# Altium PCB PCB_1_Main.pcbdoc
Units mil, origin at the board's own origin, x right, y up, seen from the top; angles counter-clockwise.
Board outline 3641.73 x 4338.58 mil, 2 copper layers (Top Layer, Bottom Layer), stack 62.206 mil thick; 67 components, 54 nets, 261 pads, 263 vias.
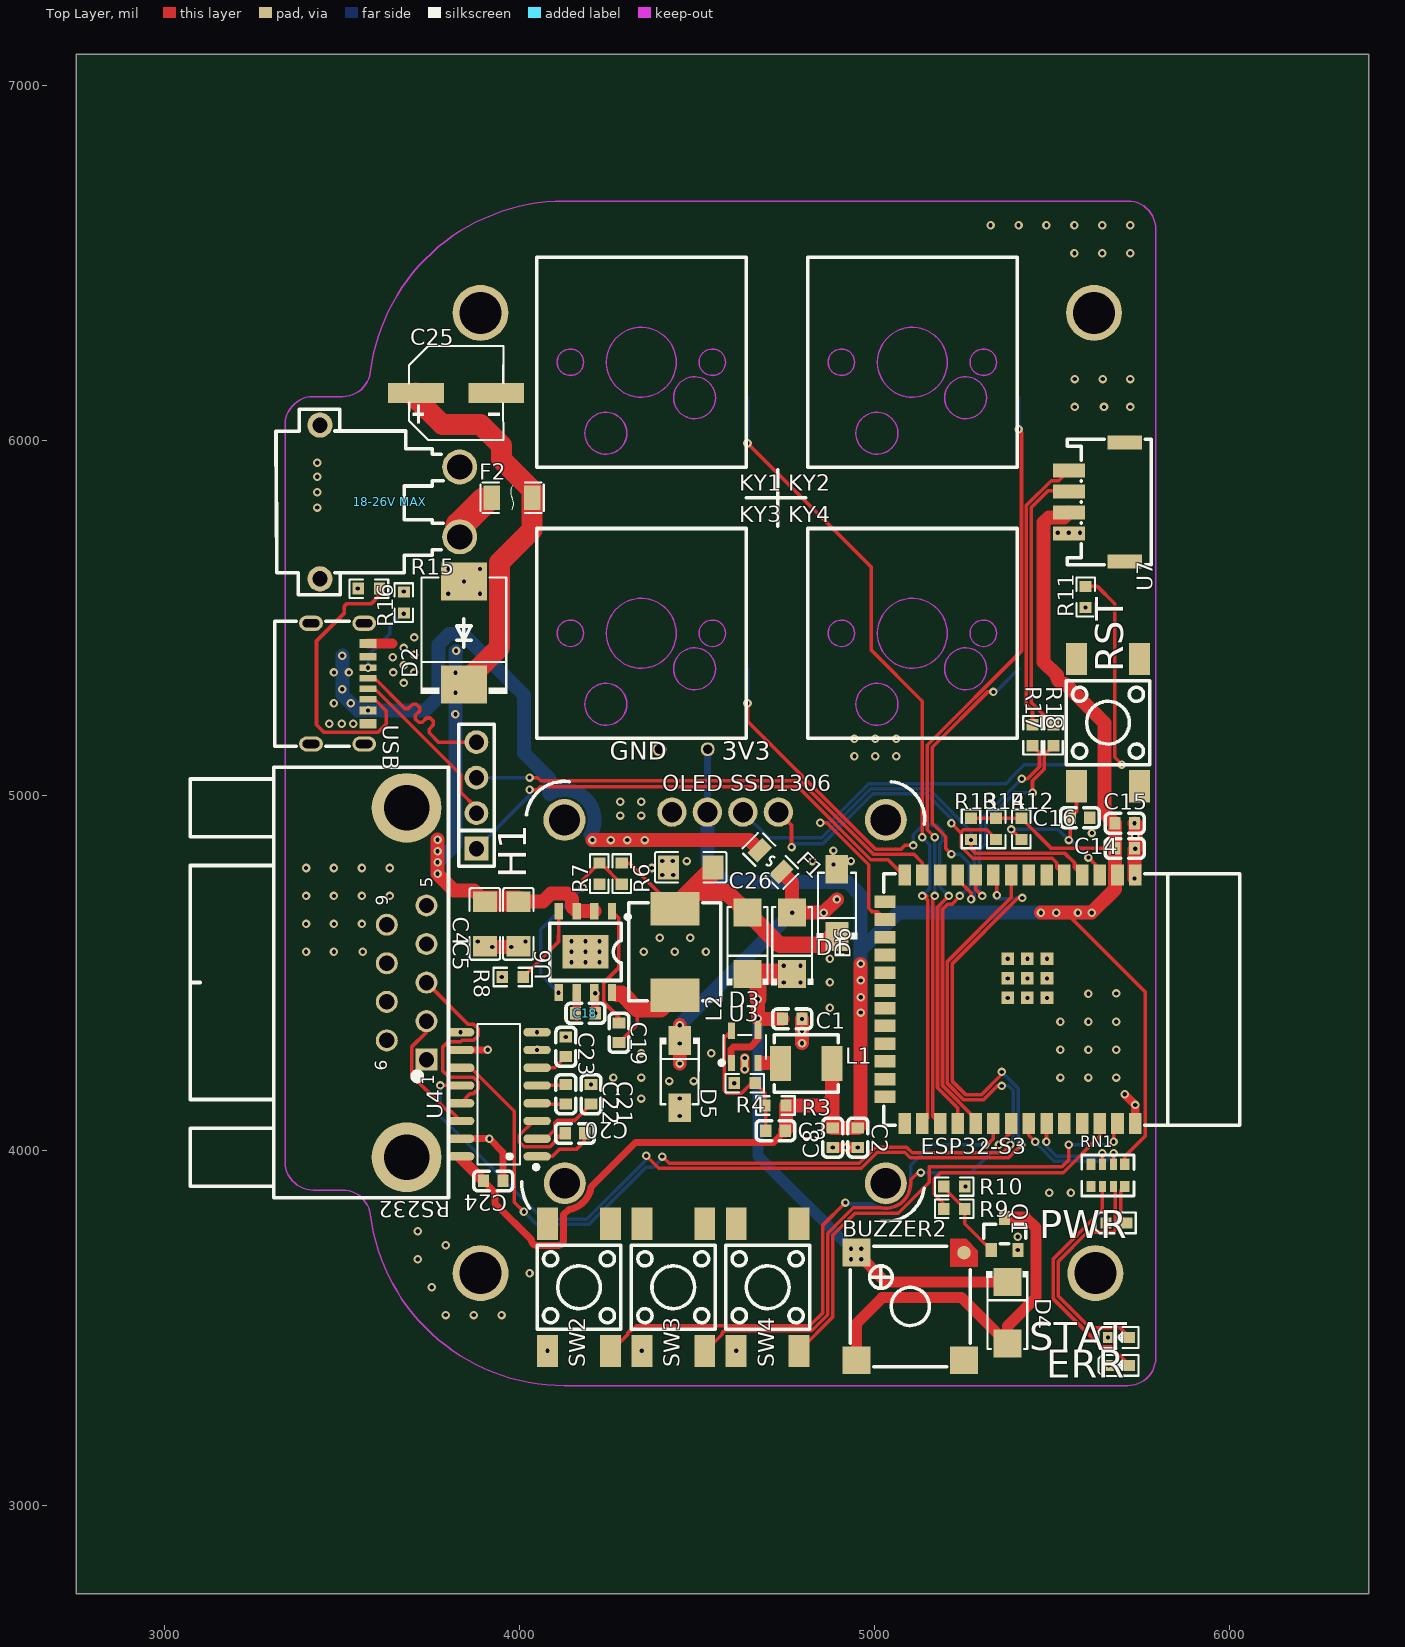
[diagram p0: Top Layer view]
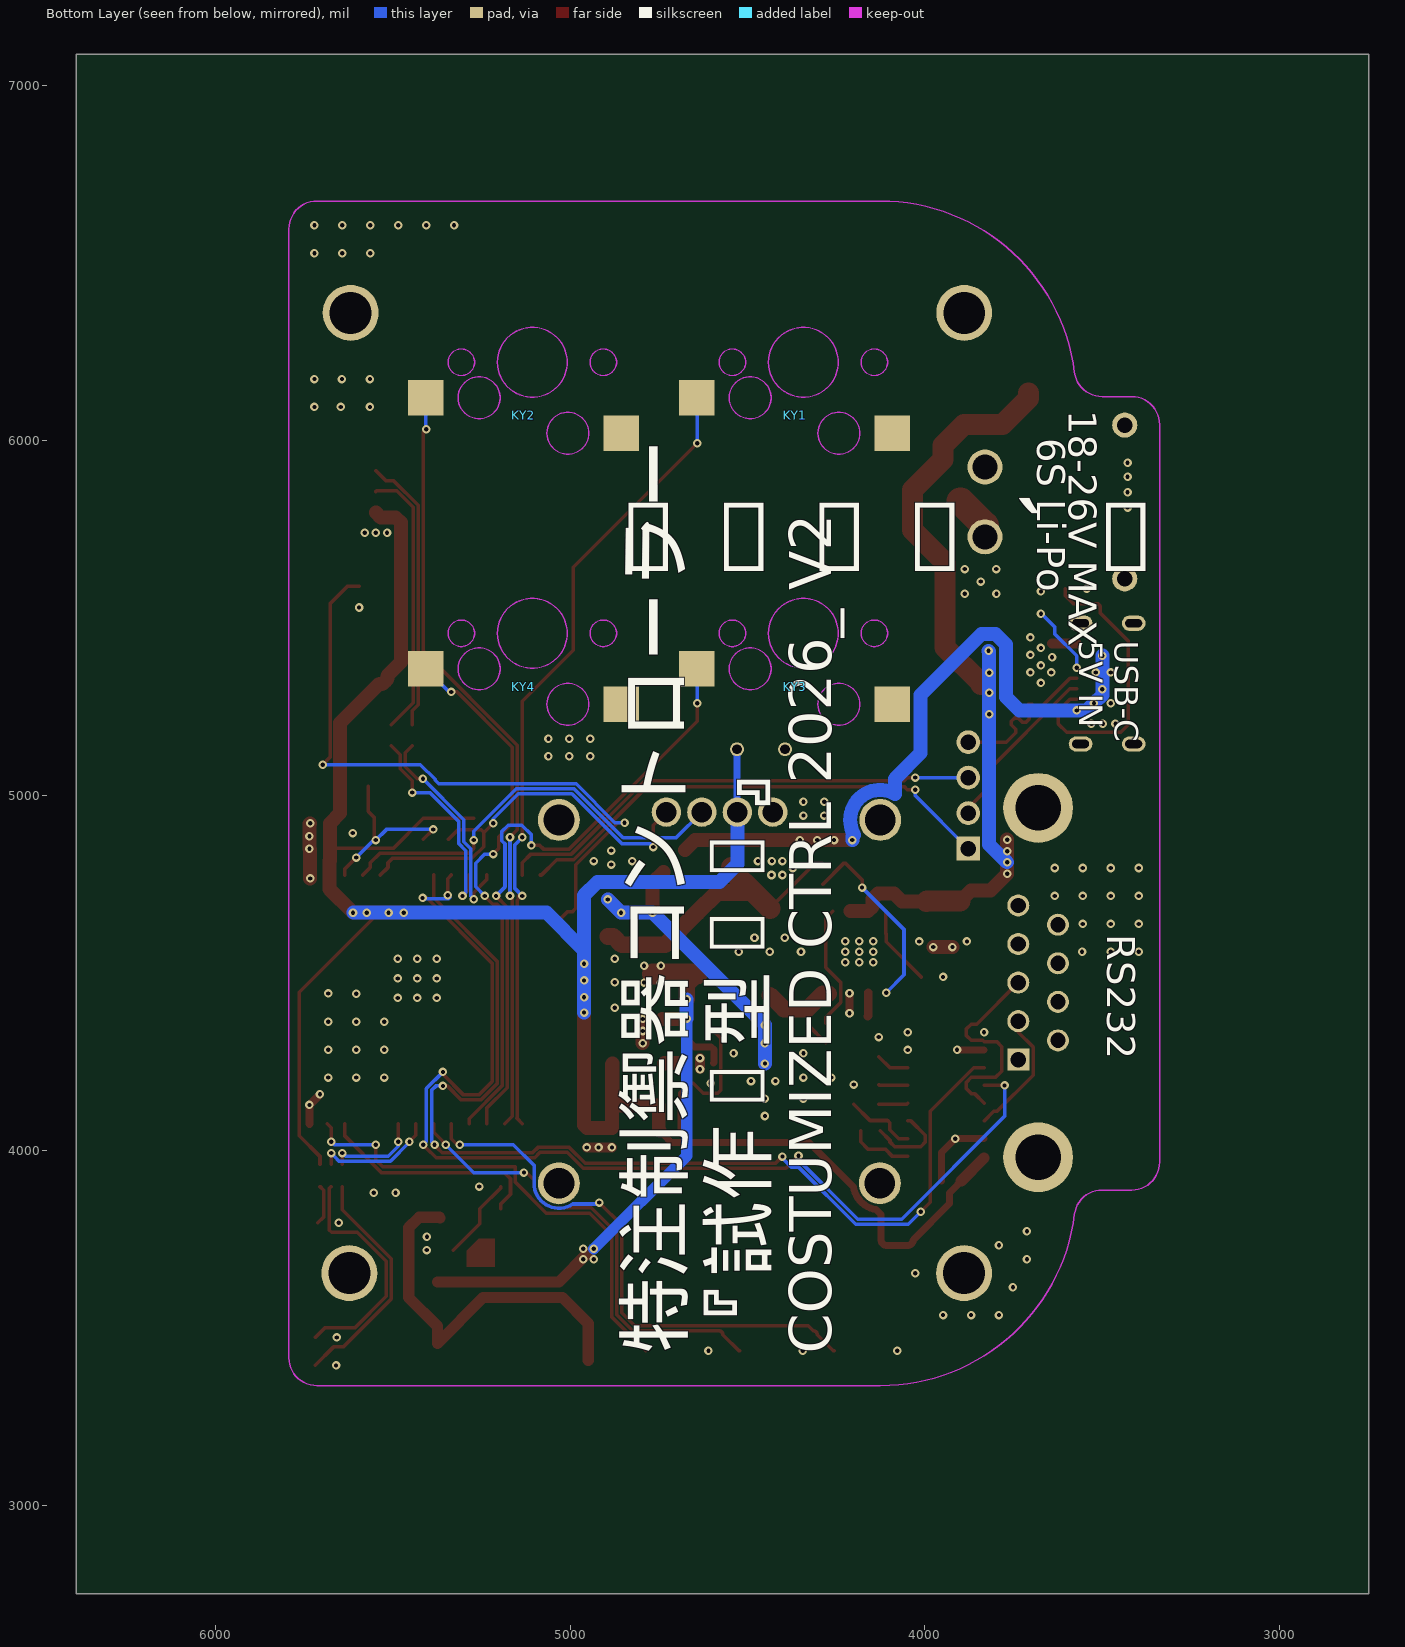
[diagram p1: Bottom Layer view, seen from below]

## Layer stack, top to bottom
Top Solder Mask Layer: solder mask 0.394, Dk 3.3
Top Layer: signal copper 1.379
Dielectric1: surface 59.449, FR4, Dk 4.5
Bottom Layer: signal copper 1.378
Bottom Solder Mask Layer: solder mask 0.394, Dk 3.3

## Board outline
6391.73,2750 2750,2750 2750,7088.58 6391.73,7088.58

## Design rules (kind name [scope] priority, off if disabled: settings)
BoardOutlineClearance copperThickness1oz [All] p0: genericclearance=10 ignorepadtopadclearanceinfootprint=FALSE except(0: Arc-SplitContinuation Track-SplitContinuation SMDPad-SplitContinuation THPad-SplitContinuation Via-SplitContinuation Fill-SplitContinuation Poly-SplitContinuation Region-SplitContinuation Text-SplitContinuation)
BoardOutlineClearance copperThickness2oz [All] p0: genericclearance=10 ignorepadtopadclearanceinfootprint=FALSE except(0: Arc-SplitContinuation Track-SplitContinuation SMDPad-SplitContinuation THPad-SplitContinuation Via-SplitContinuation Fill-SplitContinuation Poly-SplitContinuation Region-SplitContinuation Text-SplitContinuation)
BoardOutlineClearance p [All] p0: genericclearance=10 ignorepadtopadclearanceinfootprint=FALSE except(0: Arc-SplitContinuation Track-SplitContinuation SMDPad-SplitContinuation THPad-SplitContinuation Via-SplitContinuation Fill-SplitContinuation Poly-SplitContinuation Region-SplitContinuation Text-SplitContinuation)
BoardOutlineClearance otherClearance [All] p0: genericclearance=10 ignorepadtopadclearanceinfootprint=FALSE except(0: Arc-SplitContinuation Track-SplitContinuation SMDPad-SplitContinuation THPad-SplitContinuation Via-SplitContinuation Fill-SplitContinuation Poly-SplitContinuation Region-SplitContinuation Text-SplitContinuation)
Clearance copperThickness1oz [All] p1: gap=7 ignorepadtopadclearanceinfootprint=FALSE
Clearance copperThickness2oz [(InNet('USB_5V'))] p1: gap=7 ignorepadtopadclearanceinfootprint=FALSE
Clearance p [All] p1: gap=7 ignorepadtopadclearanceinfootprint=FALSE
Clearance otherClearance [All] p1: gap=7 ignorepadtopadclearanceinfootprint=FALSE
DiffPairsRouting differentialPair [All] p1: maxuncoupledlength=10 minlimit=6 maxlimit=Infinity mostfreqgap=6 toplayer_minwidth=5 toplayer_prefwidth=10 toplayer_maxwidth=100 bottomlayer_minwidth=5 bottomlayer_prefwidth=10 bottomlayer_maxwidth=100
PasteMaskExpansion pasteMaskExpansion [All] p1: expansion=0
PlaneConnect innerPlane [All] p1: planeconnectstyle=Relief reliefexpansion=20 reliefentries=4 reliefconductorwidth=10 reliefairgap=10
PolygonConnect copperRegion [All] p1: connectstyle=Relief reliefentries=4 reliefconductorwidth=10 polygonreliefangle="90 Angle" airgapwidth=10
PolygonConnect copperRegion1 [All] p1: connectstyle=Direct reliefentries=4 reliefconductorwidth=10 polygonreliefangle="90 Angle" airgapwidth=10
RoutingVias viaSize [All] p1: viastyle="Through Hole" holewidth=12.0078 minholewidth=11.811 maxholewidth=248.0314 width=12.0078 minwidth=11.811 maxwidth=248.0314
SolderMaskExpansion solderMaskExpansion [IsVia] p1: useseparateexpansions=TRUE expansion=-1000 expansionbottom=-1000
SolderMaskExpansion solderMaskExpansion [All] p2: useseparateexpansions=TRUE expansion=2 expansionbottom=2
Width copperThickness1oz [All] p1: maxlimit=100 minlimit=5 preferedwidth=10
Width copperThickness2oz [All] p1: maxlimit=100 minlimit=8 preferedwidth=10

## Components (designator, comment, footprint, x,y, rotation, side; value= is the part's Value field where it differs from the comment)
"18-26V MAX" "XT30PW-M30.G.Y" CONN-TH_XT30PW-M 3633.86,5826.77 r270 top
BUZZER2 "2.7kHz" BUZ-SMD_GSC85XX 5100.29,3559.77 r0 top
C1 "10uF" C0603 4767.72,4370.08 r180 top
C2 "10uF" C0603 4952.76,4035.43 r90 top
C3 "10uF" C0603 4720.47,4055.12 r0 top
C4 "10uF" C1206 3901.57,4637.8 r270 top
C5 "10uF" C1206 3996.06,4637.8 r270 top
C8 "10uF" C0603 4881.89,4035.43 r90 top
C14 "10uF" C0603 5704.72,4850.39 r0 top
C15 "10uF" C0603 5704.72,4921.26 r0 top
C16 "10uF" C0603 5578.74,4937.01 r180 top
C18 "10uF" C0603 4185.04,4385.83 r180 top
C19 "10uF" C0603 4279.53,4330.71 r90 top
C20 "10uF" C0603 4155.51,4047.24 r180 top
C21 "10uF" C0603 4200.79,4157.48 r90 top
C22 "10uF" C0603 4129.92,4157.48 r90 top
C23 "10uF" C0603 4129.92,4291.34 r270 top
C24 "10uF" C0603 3925.2,3913.39 r180 top
C25 "100uF" CAP-SMD_BD6.3-L6.6-W6.6-LS7.3-FD-H7.7 3820.87,6133.86 r0 top
C26 "10uF" C1206 4481.78,4797.21 r0 top
D1 "SS34" SMA_L4.3-W2.6-LS5.2-RD 4767.72,4582.68 r90 top
D2 "SMCJ33A" SMC_L6.9-W5.9-LS7.9-RD 3842.6,5457.3 r90 top
D3 "SS34" SMA_L4.3-W2.6-LS5.2-RD 4641.73,4582.68 r90 top
D4 "SS34" SMA_L4.3-W2.6-LS5.2-RD 5374.01,3542.38 r270 top
D5 "SMAJ5.0A" SMA_L4.3-W2.6-LS5.0-RD 4450.79,4214.57 r270 top
D6 "SMAJ5.0A" SMA_L4.3-W2.6-LS5.0-RD 4893.7,4696.85 r90 top
ERR "GL0603UG01" LED0603-RD 5688.98,3393.7 r0 top
ESP32-S3 "2.4GHz" WIFIM-SMD_ESP32-S3-WROOM-1-N8 5381.89,4425.2 r270 top
F1 "MF-PSMF075X-2" F0805 4706.69,4814.96 r315 top
F2 "CC12H4A-TR" F1206 3978.35,5838.58 r0 top
H1 "PZ254V-11-04P" HDR-TH_4P-P2.54-V-M 3877.95,5000 r90 top
KY1 "" 封装_凯华热插拔-5脚 4342.52,6220.47 r0 top
KY2 "" 封装_凯华热插拔-5脚 5106.3,6220.47 r0 top
KY3 "" 封装_凯华热插拔-5脚 4342.52,5456.69 r0 top
KY4 "" 封装_凯华热插拔-5脚 5106.3,5456.69 r0 top
L1 "2.2uH" IND-SMD_L4.6-W4.1_MHCI04015 4807.09,4244.09 r0 top
L2 "6.8uH" IND-SMD_L7.5-W6.6_SRG0650 4437.01,4559.06 r90 top
"OLED SSD1306" "HS96L03W2C03" OLED-TH_L27.8-W27.2-P2.54_C9900033791 4578.74,4952.76 r0 top
PWR "GL0603UG01" LED0603-RD 5681.1,3795.28 r0 top
Q1 "Si2302CDS-T1-GE3" SOT-23_L2.9-W1.3-P1.90-LS2.4-BR 5366.14,3763.78 r270 top
R3 "5.1kΩ" R0603 4720.47,4125.98 r0 top
R4 "5.1kΩ" R0603 4633.86,4188.98 r0 top
R6 "5.1kΩ" R0603 4287.4,4779.53 r90 top
R7 "5.1kΩ" R0603 4224.41,4779.53 r90 top
R8 "5.1kΩ" R0603 3980.31,4488.19 r0 top
R9 "5.1kΩ" R0603 5224.41,3834.65 r0 top
R10 "5.1kΩ" R0603 5224.41,3897.64 r0 top
R11 "5.1kΩ" R0603 5594.49,5559.06 r90 top
R12 "5.1kΩ" R0603 5413.39,4905.51 r90 top
R13 "5.1kΩ" R0603 5271.65,4905.51 r270 top
R14 "5.1kΩ" R0603 5342.52,4905.51 r90 top
R15 "5.1kΩ" R0603 3574.8,5582.68 r0 top
R16 "5.1kΩ" R0603 3673.23,5543.31 r90 top
R17 "5.1kΩ" R0603 5444.88,5169.29 r270 top
R18 "5.1kΩ" R0603 5503.94,5169.29 r270 top
RN1 "4.7kΩ" RES-ARRAY-SMD_0603-8P-L3.2-W1.6-BL 5657.48,3929.13 r180 top
RS232 "D-DMR009PF-D002" DSUB-TH_DMR-9S 3681.1,4472.44 r180 top
RST "KH-6X6X10H-STM" SW-SMD_4P-L6.0-W6.0-P4.50-LS9.0-H10.0 5657.48,5204.72 r90 top
STAT "GL0603UG01" LED0603-RD 5688.98,3472.44 r0 top
SW2 "KH-6X6X10H-STM" SW-SMD_4P-L6.0-W6.0-P4.50-LS9.0-H10.0 4166.73,3613.86 r90 top
SW3 "KH-6X6X10H-STM" SW-SMD_4P-L6.0-W6.0-P4.50-LS9.0-H10.0 4432.64,3613.86 r90 top
SW4 "KH-6X6X10H-STM" SW-SMD_4P-L6.0-W6.0-P4.50-LS9.0-H10.0 4698.54,3613.86 r90 top
U3 "SY8089A" SOT-23-5_L3.0-W1.7-P0.95-LS2.8-BL 4633.86,4291.34 r0 top
U4 "SP3232EEN-L/TR" SOIC-16_L9.9-W3.9-P1.27-LS6.0-BL 3940.94,4157.48 r90 top
U6 "SCT2432STER" ESOP-8_L4.9-W3.9-P1.27-LS6.0-BL-EP 4185.04,4559.06 r180 top
U7 "ZX-ZH1.5-4PWT" CONN-SMD_4P-P1.50_ZX-ZH1.5-4PWT 5625.98,5826.77 r90 top
USB "MC-403L68-Z20" USB-C-SMD_MC-403L68-Z20 3492.13,5314.96 r270 top

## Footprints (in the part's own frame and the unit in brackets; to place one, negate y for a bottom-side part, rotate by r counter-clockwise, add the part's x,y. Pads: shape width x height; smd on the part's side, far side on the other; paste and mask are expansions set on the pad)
BUZ-SMD_GSC85XX [mm]
  rect 2x2 smd: 1(-3.85,3.85) 2(-3.85,-3.85) 3(3.85,-3.85)
  round 0.97 smd: 4(3.85,3.85)
  Top Layer region: 4.85,2.85 2.85,2.85 2.85,4.85 4,4.85 4.85,4
  silkscreen extent -4.3,-4.3 4.3,4.3
C0603 [mm]
  rect 0.8x0.9 smd: 1(-0.7,0) 2(0.7,0)
  silkscreen extent -1.39,-0.71 1.39,0.71
C1206 [mm]
  rect 1.485x1.728 smd paste-100 mask+0.051: 1(-1.593,0) 2(1.593,0)
  silkscreen extent -2.56,-1.09 2.56,1.09
CAP-SMD_BD6.3-L6.6-W6.6-LS7.3-FD-H7.7 [mm]
  rect 4x1.4 smd: 1(-2.87,0) 2(2.87,0)
  silkscreen extent -3.38,-3.38 3.38,3.38
CONN-SMD_4P-P1.50_ZX-ZH1.5-4PWT [mm]
  rect 1x2.3 smd paste+0 mask+0.05: 1(-2.25,2) 2(-0.75,2) 3(0.75,2) 4(2.25,2)
  rect 1x2.5 smd paste+0 mask+0.05: 5(4.25,-2) 6(-4.25,-2)
  silkscreen extent -4.5,-3.9 4.5,2.1
CONN-TH_XT30PW-M [mm]
  round 2.5 hole 1.8: 1(-2.5,5) 2(2.5,5)
  round 1.8 hole 1.1: 3(5.5,-5) 4(-5.5,-5)
  silkscreen extent -6.65,-8.15 6.65,3.81
DSUB-TH_DMR-9S [mil]
  rect 62x62 hole 43.31: 1(-55.91,217.31)
  round 62 hole 43.31: 2(-55.91,108.65) 3(-55.91,-0.01) 4(-55.91,-108.66) 5(-55.91,-217.33) 6(55.91,162.98) 7(55.91,54.32) 8(55.91,-54.34) 9(55.91,-163)
  round 196.85 hole 127.95: 10(-0.01,492.12) 11(-0.01,-492.12)
  silkscreen extent -118,-606 610,606
ESOP-8_L4.9-W3.9-P1.27-LS6.0-BL-EP [mm]
  rect 0.6x1.2 smd: 1(-1.905,-2.908) 2(-0.635,-2.908) 3(0.635,-2.908) 4(1.905,-2.908) 5(1.905,2.908) 6(0.635,2.908) 7(-0.635,2.908) 8(-1.905,2.908)
  rect 3.3x2.4 smd: 9(0,0)
  silkscreen extent -3.2,-2.67 2.55,2.05
F0805 [mm]
  rect 1x1.5 smd paste-100 mask+0.051: 1(-1.1,0) 2(1.1,0)
  silkscreen extent -2.06,-1.02 2.06,1.02
F1206 [mm]
  rect 1.19x1.728 smd: 1(-1.445,0) 2(1.445,0)
  silkscreen extent -2.27,-1.09 2.27,1.09
HDR-TH_4P-P2.54-V-M [mm]
  rect 1.7x1.7 hole 1.1: 1(-3.81,0)
  round 1.7 hole 1.1: 2(-1.27,0) 3(1.27,0) 4(3.81,0)
  silkscreen extent -5.08,-1.27 5.08,1.27
IND-SMD_L4.6-W4.1_MHCI04015 [mm]
  rect 1.5x2.5 smd: 1(-1.85,0) 2(1.85,0)
  silkscreen extent -2.3,-2.05 2.3,2.05
IND-SMD_L7.5-W6.6_SRG0650 [mm]
  rect 2.4x3.5 smd: 1(-3.1,0) 2(3.1,0)
  silkscreen extent -3.5,-3.3 3.5,3.3
LED0603-RD [mm]
  rect 0.8x0.8 smd paste+0 mask+0.051: 1(-0.749,0) 2(0.749,0)
  silkscreen extent -1.49,-0.75 1.39,0.76
OLED-TH_L27.8-W27.2-P2.54_C9900033791 [mm]
  round 2.1 hole 1.45 paste+0 mask+0.05: 1(-3.81,0) 2(-1.27,0) 3(1.27,0) 4(3.81,0)
  round 3 hole 2.2: 5(-11.5,-0.56) 5(-11.475,-26.56) 5(11.5,-26.57) 5(11.5,-0.56)
  silkscreen extent -14.55,-29.3 14.28,2.2
R0603 [mil]
  rect 31.75x34.02 smd paste-3937.01 mask+2: 1(-29.66,0) 2(29.66,0)
  silkscreen extent -55,-26 55,26
RES-ARRAY-SMD_0603-8P-L3.2-W1.6-BL [mm]
  rect 0.65x0.8 smd paste+0 mask+0.051: 1(-1.2,-0.8) 4(1.2,-0.8) 5(1.2,0.8) 8(-1.2,0.8)
  rect 0.5x0.8 smd paste+0 mask+0.051: 2(-0.4,-0.8) 3(0.4,-0.8) 6(0.4,0.8) 7(-0.4,0.8)
  silkscreen extent -1.87,-1.45 1.87,1.47
SMA_L4.3-W2.6-LS5.0-RD [mm]
  rect 2.046x1.62 smd: 1(-2.404,-0.009) 2(2.404,0.009)
  silkscreen extent -2.61,-1.44 2.16,1.44
SMA_L4.3-W2.6-LS5.2-RD [mm]
  rect 2x2 smd: 1(-2.2,0) 2(2.2,0)
  silkscreen extent -2.98,-1.5 2.6,1.5
SMC_L6.9-W5.9-LS7.9-RD [mm]
  rect 2.7x3.3 smd: 1(-3.686,0) 2(3.686,0)
  silkscreen extent -4.36,-3.1 3.98,3.1
SOIC-16_L9.9-W3.9-P1.27-LS6.0-BL [mil]
  oval 23.7x77.6 smd: 1(-175,-107.7) 2(-125,-107.7) 3(-75,-107.7) 4(-25,-107.7) 5(25,-107.7) 6(75,-107.7) 7(125,-107.7) 8(175,-107.7) 9(175,107.7) 10(125,107.7) 11(75,107.7) 12(25,107.7) 13(-25,107.7) 14(-75,107.7) 15(-125,107.7) 16(-175,107.7)
  silkscreen extent -211,-111 198,60
SOT-23-5_L3.0-W1.7-P0.95-LS2.8-BL [mm]
  rect 0.49x1.157 smd: 1(-0.95,-1.154) 2(0,-1.154) 3(0.95,-1.154)
  rect 0.49x1.175 smd: 4(0.95,1.154) 5(-0.95,1.154)
  silkscreen extent -1.8,-1.29 1.53,0.85
SOT-23_L2.9-W1.3-P1.90-LS2.4-BR [mm]
  rect 1x0.8 smd: 1(1.15,-0.95) 2(1.15,0.95) 3(-1.15,0)
  silkscreen extent -0.7,-1.5 0.7,1.5
SW-SMD_4P-L6.0-W6.0-P4.50-LS9.0-H10.0 [mm]
  rect 2.3x1.5 smd: 1(-4.55,2.25) 2(4.55,2.25) 3(-4.55,-2.25) 4(4.55,-2.25)
  silkscreen extent -3,-3 3,3
USB-C-SMD_MC-403L68-Z20 [mm]
  oval 1.1x1.7 hole 0.6 slot 1.2 at 90 deg: 9(-4.32,1.76) 10(-4.32,-2.04) 11(4.32,-2.04) 12(4.32,1.76)
  rect 0.46x1.2 smd paste-100 mask+0.051: A5(-1.125,2.04) A6(-0.375,2.04) A7(0.375,2.04) B5(1.125,2.04)
  rect 0.66x1.2 smd paste-100 mask+0.051: B1(2.875,2.04) B12(-2.875,2.04)
  rect 0.56x1.2 smd paste-100 mask+0.051: B4(1.925,2.04) B9(-1.925,2.04)
  silkscreen extent -4.47,-4.64 4.47,0.69
WIFIM-SMD_ESP32-S3-WROOM-1-N8 [mm]
  rect 1.5x0.9 smd paste+0 mask+0.05: 1(-8.9,8.955) 2(-8.9,7.685) 3(-8.9,6.415) 4(-8.9,5.145) 5(-8.9,3.875) 6(-8.9,2.605) 7(-8.9,1.335) 8(-8.9,0.065) 9(-8.9,-1.205) 10(-8.9,-2.475) 11(-8.9,-3.745) 12(-8.9,-5.015) 13(-8.9,-6.285) 14(-8.9,-7.555) 27(8.9,-7.555) 28(8.9,-6.285) 29(8.9,-5.015) 30(8.9,-3.745) 31(8.9,-2.475) 32(8.9,-1.205) 33(8.9,0.065) 34(8.9,1.335) 35(8.9,2.605) 36(8.9,3.875) 37(8.9,5.145) 38(8.9,6.415) 39(8.9,7.685) 40(8.9,8.955)
  rect 0.9x1.5 smd paste+0 mask+0.05: 15(-6.985,-8.955) 16(-5.715,-8.955) 17(-4.445,-8.955) 18(-3.175,-8.955) 19(-1.905,-8.955) 20(-0.635,-8.955) 21(0.635,-8.955) 22(1.905,-8.955) 23(3.175,-8.955) 24(4.445,-8.955) 25(5.715,-8.955) 26(6.985,-8.955)
  rect 0.9x0.9 smd: 41(-2.9,1.235) 41(-2.9,2.635) 41(-2.9,-0.165) 41(-1.499,2.635) 41(-1.499,1.235) 41(-1.499,-0.165) 41(-0.099,2.635) 41(-0.099,1.235) 41(-0.099,-0.165)
  silkscreen extent -9,-9.05 9,16.45
封装_凯华热插拔-5脚 [mil]
  rect 100x100 smd far side paste+0 mask+4: 3(-250,-200) 4(300,-100)
  Board Outline Layer circle w0.1: c0,0 r98.43
  Board Outline Layer circle w0.1: c200,0 r37.4
  Board Outline Layer circle w0.1: c-200,0 r37.4
  Board Outline Layer circle w0.1: c-100,-200 r59.06
  Board Outline Layer circle w0.1: c150,-100 r59.06
  Board Outline Layer region: 98.43,0 88.68,-42.71 61.37,-76.95 21.9,-95.96 -21.9,-95.96 -61.37,-76.95 -88.68,-42.71 -98.43,0 -98.43,0 -88.68,42.71 -61.37,76.95 -21.9,95.96 21.9,95.96 61.37,76.95 88.68,42.71 98.43,0
  Board Outline Layer region: 98.43,0 88.68,-42.71 61.37,-76.95 21.9,-95.96 -21.9,-95.96 -61.37,-76.95 -88.68,-42.71 -98.43,0 -98.43,0 -88.68,42.71 -61.37,76.95 -21.9,95.96 21.9,95.96 61.37,76.95 88.68,42.71 98.43,0
  Board Outline Layer region: 237.4,0 233.7,-16.23 223.32,-29.24 208.32,-36.46 191.68,-36.46 176.68,-29.24 166.3,-16.23 162.6,0 162.6,0 166.3,16.23 176.68,29.24 191.68,36.46 208.32,36.46 223.32,29.24 233.7,16.23 237.4,0
  Board Outline Layer region: 237.4,0 233.7,-16.23 223.32,-29.24 208.32,-36.46 191.68,-36.46 176.68,-29.24 166.3,-16.23 162.6,0 162.6,0 166.3,16.23 176.68,29.24 191.68,36.46 208.32,36.46 223.32,29.24 233.7,16.23 237.4,0
  Board Outline Layer region: -162.6,0 -166.3,-16.23 -176.68,-29.24 -191.68,-36.46 -208.32,-36.46 -223.32,-29.24 -233.7,-16.23 -237.4,0 -237.4,0 -233.7,16.23 -223.32,29.24 -208.32,36.46 -191.68,36.46 -176.68,29.24 -166.3,16.23 -162.6,0
  Board Outline Layer region: -162.6,0 -166.3,-16.23 -176.68,-29.24 -191.68,-36.46 -208.32,-36.46 -223.32,-29.24 -233.7,-16.23 -237.4,0 -237.4,0 -233.7,16.23 -223.32,29.24 -208.32,36.46 -191.68,36.46 -176.68,29.24 -166.3,16.23 -162.6,0
  Board Outline Layer region: -40.94,-200 -46.79,-225.62 -63.18,-246.17 -86.86,-257.57 -113.14,-257.57 -136.82,-246.17 -153.21,-225.62 -159.06,-200 -159.06,-200 -153.21,-174.38 -136.82,-153.83 -113.14,-142.43 -86.86,-142.43 -63.18,-153.83 -46.79,-174.38 -40.94,-200
  Board Outline Layer region: -40.94,-200 -46.79,-225.62 -63.18,-246.17 -86.86,-257.57 -113.14,-257.57 -136.82,-246.17 -153.21,-225.62 -159.06,-200 -159.06,-200 -153.21,-174.38 -136.82,-153.83 -113.14,-142.43 -86.86,-142.43 -63.18,-153.83 -46.79,-174.38 -40.94,-200
  Board Outline Layer region: 209.06,-100 203.21,-125.62 186.82,-146.17 163.14,-157.57 136.86,-157.57 113.18,-146.17 96.79,-125.62 90.94,-100 90.94,-100 96.79,-74.38 113.18,-53.83 136.86,-42.43 163.14,-42.43 186.82,-53.83 203.21,-74.38 209.06,-100
  Board Outline Layer region: 209.06,-100 203.21,-125.62 186.82,-146.17 163.14,-157.57 136.86,-157.57 113.18,-146.17 96.79,-125.62 90.94,-100 90.94,-100 96.79,-74.38 113.18,-53.83 136.86,-42.43 163.14,-42.43 186.82,-53.83 203.21,-74.38 209.06,-100
  silkscreen extent -295,-295 295,295

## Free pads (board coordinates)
  round 157.48 hole 118.11: 1(3889.28,6359.78) 1(3889.76,3653.54) 1(5618.22,6359.78) 1(5622.05,3653.54)
  round 39.37 hole 27.56 paste+0 mask+2: 1(4393.97,5129.92) 1(4529.53,5129.92)

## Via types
v1: diameter 24.02, hole 12.01, Top Layer to Bottom Layer, 263 vias

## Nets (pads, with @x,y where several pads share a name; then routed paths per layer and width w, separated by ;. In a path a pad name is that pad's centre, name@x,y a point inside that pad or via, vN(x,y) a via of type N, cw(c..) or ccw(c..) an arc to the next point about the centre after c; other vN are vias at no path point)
3V3: "OLED SSD1306.2" C2.2 C3.2 C8.2 C14.1 C15.1 C24.2 ESP32-S3.2 L1.2 pad.1@4529.53,5129.92 R3.2 R12.2 R13.1 R14.2 RN1.1 U4.16 U7.2 | length 6771.9
  Top Layer w10: R13.1 R14.2 R12.2 5498.16,4850.39 C14.1 ; 5539.37,4669.29 5763.14,4445.53 5763.14,4040.73 5704.72,3982.32 RN1.1
  Top Layer w19.68: C24.2 3921.18,3889.84 3921.18,3889.11 3930.45,3879.84 3930.45,3850.06 4032.8,3747.71 ccw(c4048.63,3747.71) 4048.63,3731.88 4107.69,3731.88 ccw(c4107.69,3747.71) 4123.51,3747.71 4123.51,3818.39 4138.16,3833.05 ccw(c4126.97,3907.09) 4201.01,3895.89 4326.69,4021.57 4715.22,4021.57 4724.49,4030.85 4724.49,4031.57 C3.2
  Top Layer w31.5: U4.16@3833.24,3977.78 C24.2
  Top Layer w39.37: C3.2 4750.13,4057.22 R3.2 4862.2,4125.98 4879.92,4143.7 L1.2 4881.89,4242.12 C8.2 C2.2 4960.63,4070.87 v1(4960.63,4387.92) v1(4960.63,4431.35) v1(4960.63,4478.52) v1(4960.63,4525.19) ; v1(5468.5,4669.29) v1(5511.56,4669.29) 5539.37,4669.29 v1(5573,4669.29) v1(5611.69,4669.29) 5677.82,4735.42 5677.82,4815.74 5677.16,4816.4 C14.1 C15.1 5647.72,4950.71 5647.72,5204.57 5539.38,5312.91 cw(c5539.38,5338.58) 5513.71,5338.58 5476.3,5375.99 5476.3,5768.5 5491.34,5783.54 5533.54,5783.54 U7.2
  Bottom Layer w19.68: 4528.74,4952.76 4529.53,4953.54 pad.1@4529.53,5129.92
  Bottom Layer w39.37: 4528.74,4952.76 4528.74,4805.91 4578.74,4755.91 4923.23,4755.91 4960.63,4718.5 4960.63,4563 ; v1(4960.63,4387.92) v1(4960.63,4431.35) v1(4960.63,4478.52) v1(4960.63,4525.19) 4960.63,4563 ; v1@5610.24,4669.29 v1(5573,4669.29) v1(5511.56,4669.29) v1(5468.5,4669.29) 5066.93,4669.29 4960.63,4563
5V: BUZZER2.1 C1.2 D1.1 D3.1 D4.1 U3.1 U3.4 | length 1754.2
  Top Layer w19.68: U3.1 4594.69,4247.69 4594.69,4283.66 4602.36,4291.34 4649.61,4291.34 4671.26,4312.99 U3.4
  Top Layer w31.5: BUZZER2.1 5031.07,3628.99 D4.1
  Top Layer w39.37: v1(4671.26,4425.24) v1(4671.26,4371.02) 4672.2,4370.08 C1.2
  Top Layer w47.24: D3.1 4671.26,4466.54 v1(4671.26,4425.24)
  Top Layer w59.06: D3.1 D1.1
  Bottom Layer w31.5: v1(4671.26,4371.02) 4671.26,3984.25 v1(4933.07,3722.44)
  Bottom Layer w39.37: v1(4671.26,4371.02) v1(4671.26,4425.24)
  other v1: 4933.07,3692.91 4962.6,3692.91 4962.6,3722.44 4744.09,4472.44 4791.34,4472.44 4744.09,4519.68 4791.34,4519.68
6S_IN: C4.1 C5.1 C25.1 D2.1 F2.2 U6.2 U6.3 | length 2330.2
  Top Layer w39.37: v1(3768.35,4874.99) v1(3768.35,4842.61) v1(3768.35,4811.53) v1(3768.35,4778.87) 3814.94,4732.28 3870.74,4732.28 C4.1@3901.26,4701.77 ; C5.1 4065.24,4700.5 4087.6,4722.85 4132.48,4722.85 4147.52,4707.81 4147.52,4686.07 U6.3 U6.2
  Top Layer w59.06: C25.1 3707.87,6118.9 3781.5,6045.28 3889.76,6045.28 3948.82,5986.22 3948.82,5946.85 4034.94,5860.73 4034.94,5795.19 4034.94,5747.45 3943.07,5655.58 3943.07,5416.92 3842.6,5316.44 D2.1 ; C4.1@3901.26,4701.77 3994.79,4701.77 C5.1
  Bottom Layer w39.37: v1(3768.35,4811.53) 3818.82,4861.99 v1(3818.82,5228.91) v1(3818.82,5289.31) v1(3818.82,5345.14) 3818.82,5405.43 v1(3820.58,5407.2)
$1N23: L1.1 U3.3 | length 55
  Top Layer w39.37: 4681.1,4245.92 4734.26,4245.92 L1.1
$1N30: C3.1 R3.1 R4.2 U3.5 | length 425
  Top Layer w10: U3.5 4575.83,4316.13 4575.83,4168.93 4583.77,4160.98 4624.62,4160.98 4652.62,4188.98 R4.2 4690.81,4161.68 R3.1 4692.91,4123.88 C3.1
$1N36: C19.2 U6.1 | length 358.4
  Top Layer w10: U6.1 4279.53,4654.07 4279.53,4515.01 4237.24,4472.73 4237.24,4416.38 4279.53,4374.1 C19.2
$1N37: C19.1 L2.1 U6.8 | length 315.3
  Top Layer w10: C19.1 4330.77,4354.39 4330.77,4397.58
  Top Layer w47.24: U6.8@4271.65,4440.94 4287.4,4440.94 4330.77,4397.58 4397.58,4397.58 L2.1
$1N38: C26.2 D3.2 D6.1 L2.2 R6.2 | length 845.9
  Top Layer w10: R6.2 4308.93,4809.19 L2.2
  Top Layer w47.24: L2.2@4482.28,4726.38 4584.64,4726.38 D3.2 4732.28,4578.74 4854.53,4578.74 4878,4602.21 D6.1
  Top Layer w59.06: L2.2 4482.28,4726.38 4544.48,4788.58 C26.2
$1N42: R6.1 R7.2 U6.5 | length 542.1
  Top Layer w10: v1(4177.17,4740.16) 4177.17,4761.94 R7.2 4228.08,4809.19 R6.1
  Bottom Layer w10: v1(4109.27,4443.92) 4059.06,4494.14 4059.06,4622.05 v1(4177.17,4740.16)
$1N45: C18.2 U6.6 | length 67.2
  Top Layer w23.62: U6.6 4160.04,4379.33 C18.2@4161.42,4377.95
$1N46: R8.2 U6.4 | length 226.6
  Top Layer w10: R8.2 4109.09,4587.31 4109.09,4606.3 cw(c4120.08,4606.3) 4110.04,4610.76 U6.4
$1N56: C20.1 U4.1 | length 181
  Top Layer w10: U4.1 4091.51,3982.48 4112.3,4003.27 4160.75,4003.27 4181.1,4023.62 C20.1@4181.1,4055.12
$1N57: C20.2 U4.3 | length 239.7
  Top Layer w10: U4.3 4039.4,4082.48 3998.86,4041.94 3998.86,4023.02 4012.24,4009.65 4085.05,4009.65 4098.43,4023.02 4098.43,4027.56 C20.2@4125.98,4055.12
$1N58: C21.1 U4.2 | length 203.9
  Top Layer w10: U4.2 4073.76,4032.48 4098.88,4057.6 4098.88,4077.01 4105.69,4083.82 4154.69,4083.82 C21.1
$1N60: C22.2 U4.5 | length 82.3
  Top Layer w10: U4.5 4127.36,4182.48 C22.2
$1N61: C22.1 U4.4 | length 82.3
  Top Layer w10: U4.4 4051.2,4129.92 C22.1
$1N62: C23.2 U4.6 | length 94.2
  Top Layer w10: U4.6 4098.62,4232.48 C23.2
$1N81: Q1.1 R9.2 R10.1 | length 234.6
  Top Layer w10: R10.1 5194.75,3893.97 R9.2 5254.07,3793.18 Q1.1
$1N82: BUZZER2.2 D4.2 Q1.3 | length 1073.2
  Top Layer w31.5: BUZZER2.2 4948.72,3511.71 5021.65,3584.65 5245.13,3584.65 D4.2 5374.01,3503.93 5454.72,3584.65 5454.72,3781.5 5425.2,3811.02 5368.11,3811.02 Q1.3
$1N111: ESP32-S3.16 R11.2 | length 1851.7
  Top Layer w10: v1(4846.46,4922.83) 4865.43,4922.83 4983.83,4804.43 4983.83,4681.49 4993.83,4671.49 5008.05,4671.49 ESP32-S3.16 ; R11.2 5627.82,5588.72 5676.42,5540.12 5676.42,5107.05 v1(5696.85,5086.61)
  Bottom Layer w10: v1(4846.46,4922.83) 4873.62,4922.83 4983.03,5032.25 5370.33,5032.25 5380.33,5042.24 5380.33,5044.98 5421.97,5086.61 v1(5696.85,5086.61)
$1N118: ESP32-S3.13 H1.3 | length 1390.6
  Top Layer w10: v1(4027.56,5050) 4049.57,5050 4058.69,5040.87 4789.83,5040.87 4996.06,4834.65 5110.24,4834.65 5134.43,4810.45 ESP32-S3.13
  Bottom Layer w10: H1.3 v1(4027.56,5050)
$1N119: ESP32-S3.14 H1.1 | length 1391.6
  Top Layer w10: v1(4027.56,5015.75) 4049.57,5015.75 4058.69,5024.87 4783.21,5024.87 4989.44,4818.65 5037.65,4818.65 5080.72,4775.58 ESP32-S3.14
  Bottom Layer w10: H1.1 4027.56,4999.61 v1(4027.56,5015.75)
$1N151: PWR.2 RN1.8 | length 113.6
  Top Layer w10: RN1.8 5694.06,3886.97 5694.06,3811.81 PWR.2
$1N152: RN1.7 STAT.2 | length 668.9
  Top Layer w10: RN1.7 5678.34,3892.53 5678.34,3774.98 5671.91,3768.54 5599.25,3768.54 5517.95,3687.24 5517.95,3588.35 5607.13,3499.17 5691.73,3499.17 STAT.2
$1N153: ERR.2 RN1.6 | length 665.8
  Top Layer w10: RN1.6 5641.73,3832.43 5503.94,3694.64 5503.94,3580.96 5639.18,3445.71 5666.45,3445.71 ERR.2
$1N162: R15.2 USB.B5 | length 814.7
  Top Layer w10: USB.B5 3591.12,5270.67 3624.02,5237.78 3624.02,5201.2 3600.61,5177.79 3448.15,5177.84 3427.17,5198.82 3427.17,5435.04 3505.91,5513.78 3505.91,5533.46 3512.98,5540.54 3582.01,5540.54 3604.46,5562.99 R15.2
$1N186: R16.1 USB.A5 | length 196.3
  Bottom Layer w10: v1(3572.44,5359.25) 3572.44,5393.31 3633.86,5454.72 3633.86,5474.41 v1@3673.23,5513.78
  other v1: 3673.23,5512.01
$1N189: ESP32-S3.11 R17.2 | length 614.1
  Top Layer w10: ESP32-S3.11 5234.43,4762.8 5271.65,4725.58 v1(5271.65,4706.97) ; v1(5414.65,5046.78) 5430.64,5046.78 5464.57,5080.71 5464.57,5119.95 R17.2
  Bottom Layer w10: v1(5271.65,4706.97) 5280.16,4715.47 5280.16,4850 5299.13,4868.98 5299.13,4931.26 v1(5414.65,5046.78)
$1N191: ESP32-S3.10 R18.2 | length 609.4
  Top Layer w10: ESP32-S3.10 5284.43,4735.25 v1(5303.15,4716.54) ; v1(5444.88,5007.87) 5444.88,5041.2 5478.58,5074.9 5478.58,5114.28 R18.2
  Bottom Layer w10: v1(5303.15,4716.54) 5294.17,4725.51 5294.17,4844.2 5313.15,4863.17 5313.15,4925.45 5395.57,5007.87 v1(5444.88,5007.87)
$1N195: D1.2 D5.1 F1.2 | length 1075.3
  Top Layer w39.37: v1(4450.79,4244.09) v1(4450.79,4300.78) v1(4450.79,4352.36) ; F1.2 4767.72,4753.94 v1(4767.72,4669.29) v1(4856.3,4669.29) v1(4893.7,4706.69)
  Bottom Layer w39.37: v1(4450.79,4244.09) v1(4450.79,4300.78) v1(4450.79,4352.36) v1(4767.72,4669.29) v1(4856.3,4669.29) v1(4893.7,4706.69)
$1N196: "18-26V MAX.2" F2.1 | length 128.9
  Top Layer w78.74: 3830.71,5728.35 3830.71,5759.84 F2.1@3899.61,5828.74
BZR: ESP32-S3.38 R9.1 | length 647.1
  Top Layer w10: R9.1 5194.75,3849.22 5167.89,3876.08 5167.89,3919.2 5185.7,3937.01 5531.5,3937.01 5634.43,4039.95 ESP32-S3.38
D+: H1.4 USB.A6 | length 472.8
  Top Layer w10: USB.A6 3591.12,5329.72 3676.08,5244.77 3686.08,5244.77 3698.35,5257.04 3708.35,5257.04 3717.84,5247.55 3717.84,5237.55 3705.56,5225.28 3705.56,5215.28 3715.05,5205.79 3725.05,5205.79 3737.32,5218.06 3747.32,5218.06 3756.81,5208.57 3756.81,5198.57 3744.54,5186.3 3744.54,5176.3 3770.84,5150 H1.4
D-: H1.2 USB.A7 | length 472.8
  Top Layer w10: USB.A7 3591.54,5300.19 3833.5,5058.23 3833.5,5009.02 3876.52,4966 H1.2@3877.95,4966
EN: C16.2 ESP32-S3.3 R12.1 RST.1 | length 512.6
  Top Layer w10: v1(5385.29,4903.94) R12.1 ; v1(5547.24,4874.02) 5551.18,4877.95 C16.2 5568.9,4954.72 RST.1 ; v1(5602.36,4824.8) 5634.43,4792.73 ESP32-S3.3
  Bottom Layer w10: v1(5385.29,4903.94) 5517.32,4903.94 v1(5547.24,4874.02) 5553.15,4874.02 v1(5602.36,4824.8)
GND: "18-26V MAX.1" "OLED SSD1306.1" C1.1 C2.1 C4.2 C5.2 C8.1 C14.2 C15.2 C16.1 C18.1 C21.2 C23.1 C24.1 C25.2 C26.1 D2.2 D5.2 D6.2 ERR.1 ESP32-S3.1 ESP32-S3.40 ESP32-S3.41 KY1.3 KY2.3 KY3.3 KY4.3 pad.1@3889.28,6359.78 pad.1@3889.76,3653.54 pad.1@4393.97,5129.92 pad.1@5618.22,6359.78 pad.1@5622.05,3653.54 PWR.1 Q1.2 R4.1 R7.1 R8.1 R10.2 R11.1 R15.1 R16.2 RS232.5 RST.3 STAT.1 SW2.1 SW3.1 SW4.1 U3.2 U4.7 U4.8 U4.9 U4.10 U4.15 U6.7 U6.9 U7.1 USB.B1 USB.B12 | length 895.1
  Top Layer w19.68: U4.15 v1(3914.39,4032.48) 3952.76,3994.11 C24.1 ; U4.10 3908.46,4282.48 v1(3909.45,4283.46)
  Top Layer w23.62: v1(4212.6,4385.83) v1(4212.6,4441.99) ; v1(5704.72,4157.48) v1(5734.43,4127.77) ESP32-S3.40
  Top Layer w27.56: USB.B12 3641.73,5428.15 ; v1(4633.86,4228.35) v1(4633.86,4259.84) ; v1(4881.89,4007.87) v1(4919.67,4007.87) v1(4952.76,4007.87)
  Top Layer w39.37: v1(3922.37,4572.64) v1(3976.28,4572.64) ; v1(4795.28,4301.45) v1(4795.28,4336) v1(4795.28,4370.08) ; v1(5732.28,4766) 5732.28,4847.57 v1(5734.43,4849.72) v1(5734.43,4884.91) 5734.43,4919.11 v1(5732.28,4921.26)
  other v1: 5659.48,3393.7 4078.15,3434.73 4344.05,3434.73 4609.96,3434.73 5657.48,3472.3 3791.34,3535.43 3870.08,3535.43 3948.82,3535.43 3751.97,3614.17 4027.56,3653.54 3712.6,3692.91 5403.54,3718.5 3791.34,3732.28 5403.24,3755.85 3712.6,3771.65 5651.61,3795.28 5491.85,3879.92 5553.15,3879.92 5255.71,3897.64 4450.79,4096.46 4342.52,4145.67 4450.79,4145.67 4200.79,4185.04 4604.2,4188.98 4421.26,4194.88 4490.16,4194.88 4263.78,4204.72 4342.52,4204.72 5523.62,4204.72 5602.36,4204.72 5681.1,4204.72 4342.52,4273.62 4539.37,4273.62 4048.64,4282.48 5523.62,4283.46 5602.36,4283.46 5681.1,4283.46 4129.92,4318.9 3833.24,4332.48 4048.64,4332.48 5523.62,4362.2 5602.36,4362.2 5681.1,4362.2 4874.02,4401.57 5375.39,4429.11 5430.51,4429.11 5485.63,4429.11 5602.36,4440.94 5681.1,4441.78 4874.02,4473.49 5375.39,4484.23 5430.51,4484.23 5485.63,4484.23 3949.02,4488.19 4145.67,4529.53 4185.04,4529.53 4224.41,4529.53 4874.02,4539.37 5375.39,4539.35 5430.51,4539.35 5485.63,4539.35 3397.64,4559.06 3476.38,4559.06 3557.32,4559.06 4145.67,4559.06 4185.04,4559.06 4224.41,4559.06 4349.23,4559.06 4437.01,4559.06 4524.5,4559.06 3881.66,4588.39 4015.86,4588.39 4145.67,4588.58 4185.04,4588.58 4224.41,4588.58 4394.72,4598.43 4480.31,4598.43 3397.64,4637.8 3476.38,4637.8 3555.12,4637.8 3397.64,4716.54 3476.38,4716.54 3555.12,4716.54 3633.86,4716.54 4401.57,4775.59 4432.38,4775.59 3397.64,4795.28 3476.38,4795.28 3555.12,4795.28 3633.86,4795.28 4372.05,4795.28 4883.86,4805.12 4401.57,4814.96 4431.1,4814.96 4470.47,4814.96 4824.8,4814.96 4933.07,4814.96 4883.86,4844.49 5612.2,4893.7 4283.46,4942.91 4342.52,4942.91 4283.46,4982.28 4342.52,4982.28 4942.91,5110.24 5001.97,5110.24 5061.02,5110.24 4942.91,5159.45 5001.97,5159.45 5061.02,5159.45 3463.13,5201.77 3498.27,5201.77 3530.91,5201.77 3673.23,5316.93 3643.7,5346.46 3702.76,5346.46 3673.23,5366.14 3641.73,5389.15 3702.76,5395.67 3673.23,5415.35 3702.76,5444.88 5594.49,5529.4 3798.45,5568.2 3888.17,5568.2 3673.23,5574.61 3543.5,5582.68 3842.6,5602.43 3799.21,5637.8 3888.17,5637.8 5515.75,5740.16 5547.24,5740.16 5578.74,5740.16 3429.13,5811.02 3429.13,5854.16 3429.13,5897.64 3429.13,5937.01 5563.89,6094.49 5646.3,6094.49 5720.47,6094.49 5563.89,6173.23 5642.86,6173.23 5720.47,6173.23 5562.99,6527.56 5641.73,6527.56 5720.47,6527.56 5326.77,6606.3 5405.51,6606.3 5484.25,6606.3 5562.99,6606.3 5641.73,6606.3 5720.47,6606.3
KEY1: ESP32-S3.28 KY1.4 | length 2286.8
  Top Layer w10: v1(4641.73,5992.13) 4991.06,5642.8 4991.06,5408.96 5134.43,5265.59 v1(5134.43,4881.89) ; ESP32-S3.28 5149.52,4089.9 5149.12,4090.31 5149.12,4704.19 5146.3,4707.01 5146.3,4716.54 v1(5134.43,4716.54)
  Bottom Layer w10: v1(4641.73,5992.13) 4641.73,6119.68 KY1.4 ; v1(5134.43,4716.54) 5155.28,4737.38 5155.28,4861.05 v1(5134.43,4881.89)
KEY2: ESP32-S3.29 KY2.4 | length 2179.4
  Top Layer w10: v1(5169.29,4716.54) 5163.14,4710.38 5163.14,4096.11 ESP32-S3.29 ; v1(5169.29,4881.89) 5148.45,4902.73 5148.45,5141.55 5413.84,5406.94 5413.84,6023.17 v1(5405.51,6031.5)
  Bottom Layer w10: v1(5169.29,4716.54) v1(5169.29,4881.89) ; v1(5405.51,6031.5) 5406.3,6032.28 KY2.4
KEY3: ESP32-S3.30 KY3.4 | length 1775.4
  Top Layer w10: v1(4641.73,5259.84) 4641.73,5208.8 5001.87,4848.66 5075.04,4848.66 5085.16,4858.78 v1(5108.78,4858.78) ; v1(5208.66,4716.54) 5177.15,4685.03 5177.15,4176.42 5234.43,4119.13 ESP32-S3.30
  Bottom Layer w10: v1(4641.73,5259.84) 4641.73,5355.91 KY3.4 ; v1(5108.78,4858.78) 5108.78,4888.75 5136.25,4916.22 5174.33,4916.22 5192.28,4898.27 5192.28,4872.37 5183.31,4863.39 5183.31,4741.89 v1(5208.66,4716.54)
KEY4: ESP32-S3.31 KY4.4 | length 1530.2
  Top Layer w10: v1(5216.54,4834.65) 5200.79,4850.39 5200.79,4882.91 5162.47,4921.23 5162.47,5135.75 5318.06,5291.34 v1(5334.65,5291.34) ; v1(5240.16,4716.54) 5240.16,4715.52 5218.19,4693.54 5205.49,4693.54 5191.17,4679.22 5191.17,4182.22 5284.43,4088.95 ESP32-S3.31
  Bottom Layer w10: v1(5216.54,4834.65) 5240.16,4834.65 5266.14,4808.66 5266.14,4742.52 v1(5240.16,4716.54) ; v1(5334.65,5291.34) 5340.94,5291.34 KY4.4
KEY5: ESP32-S3.32 SW2.3 | length 1566.9
  Top Layer w10: SW2.3 4258.27,3434.73 4303.54,3480 cw(c4314.53,3480) 4314.53,3490.99 4328.54,3505 4817.42,3505 4854.33,3541.92 4854.33,3789.1 v1(4917.6,3852.37) ; v1(5311.02,4015.75) 5317.88,4015.75 5334.43,4032.3 ESP32-S3.32
  Bottom Layer w10: v1(4917.6,3852.37) 4921.44,3848.52 4992.49,3848.52 ccw(c5031.5,3906.69) 5101.53,3906.69 5101.53,3957.56 5159.72,4015.75 v1(5311.02,4015.75)
KEY6: ESP32-S3.33 SW3.3 | length 1296.8
  Top Layer w10: SW3.3 4524.17,3434.73 4569.45,3480 cw(c4580.43,3480) 4580.43,3490.99 4823.22,3490.99 4868.35,3536.11 4868.35,3765.98 4940.18,3837.82 5018.78,3837.82 ccw(c5031.5,3906.69) 5101.53,3906.69 5101.53,3916.77 5121.78,3937.01 v1(5129.92,3937.01) ; v1(5350.39,4015.75) 5358.9,4024.25 5358.9,4025.27 5384.43,4050.81 ESP32-S3.33
  Bottom Layer w10: v1(5129.92,3937.01) 5271.65,3937.01 v1(5350.39,4015.75)
KEY7: ESP32-S3.39 SW4.3 | length 1372.1
  Top Layer w10: SW4.3 4882.36,3529.96 4882.36,3760.18 4944.46,3822.28 5066.66,3822.28 5153.9,3909.52 5153.9,3953.11 5527.78,3953.11 5547.24,3972.58 v1(5547.24,4015.75) ; v1(5673.23,4023.62) 5673.23,4063.61 ESP32-S3.39
  Bottom Layer w10: v1(5547.24,4015.75) 5547.87,4015.12 5664.72,4015.12 v1(5673.23,4023.62)
LED_ERR: ESP32-S3.35 RN1.3 | length 268.2
  Top Layer w10: v1(5484.25,4023.62) 5484.25,4074.63 ESP32-S3.35 ; RN1.3 v1(5641.73,3992.13)
  Bottom Layer w10: v1(5484.25,4023.62) 5484.25,4010.93 5512.03,3983.15 5632.75,3983.15 v1(5641.73,3992.13)
LED_STAT: ESP32-S3.34 RN1.2 | length 344
  Top Layer w10: ESP32-S3.34 5434.43,4041.94 v1(5452.76,4023.62) ; RN1.2 v1(5673.23,3992.13)
  Bottom Layer w10: v1(5452.76,4023.62) 5452.76,4022.6 5506.22,3969.13 5651.25,3969.13 5664.72,3982.6 5664.72,3983.62 v1(5673.23,3992.13)
R1_IN: RS232.3 U4.13 | length 598.3
  Top Layer w10: RS232.3 3854.14,4355.31 3869.65,4355.31 3883.03,4341.94 3883.03,4323.02 3869.65,4309.65 3837.58,4309.65 3833.24,4305.31 3796.84,4305.31 3783.46,4291.94 3783.46,4223.02 3801.17,4205.31 3869.65,4205.31 3883.03,4191.94 3883.03,4173.02 3869.65,4159.65 3860.41,4159.65 U4.13
SCL: "OLED SSD1306.3" ESP32-S3.4 R13.2 | length 1181.1
  Top Layer w10: R13.2 5271.65,4850.39 5285.67,4836.38 5536.42,4836.38 5563.14,4809.66 5563.14,4796.88 ESP32-S3.4
  Bottom Layer w10: 4628.74,4952.76 4701.34,4880.16 4850.77,4880.16 4988.84,5018.23 5152.08,5018.23 5271.65,4898.66 v1(5271.65,4874.02)
SDA: "OLED SSD1306.4" ESP32-S3.5 R14.1 | length 1190.7
  Top Layer w10: 4728.74,4952.76 4765.75,4915.75 v1(4765.75,4854.33) ; v1(5216.54,4921.26) 5241.52,4896.28 5243.66,4896.28 ; R14.1 5315.66,4902.71 5250.1,4902.71 5243.66,4896.28 ; ESP32-S3.5 5513.14,4796.88 5513.14,4809.66 5500.43,4822.36 5276.73,4822.36 5243.66,4855.43 5243.66,4896.28
  Bottom Layer w10: v1(4765.75,4854.33) 4775.59,4864.17 4854.6,4864.17 4994.64,5004.21 5146.28,5004.21 5216.54,4933.95 v1(5216.54,4921.26)
T1_OUT: RS232.2 U4.14 | length 361.4
  Top Layer w10: RS232.2 3737.01,4332.66 3695.02,4290.68 3695.02,4211.46 3796.84,4109.65 3806.08,4109.65 U4.14
UART1_RX: R17.1 U7.4 | length 785.5
  Top Layer w10: R17.1 5444.88,5238.19 5427.85,5255.21 5427.85,5817.4 5497.42,5886.97 5518.85,5886.97 U7.4
UART1_TX: R18.1 U7.3 | length 763.9
  Top Layer w10: R18.1 5441.87,5261.02 5441.87,5811.6 5488.54,5858.27 5545.27,5858.27 U7.3
UART2_RX: ESP32-S3.9 U4.12 | length 3206.6
  Top Layer w10: v1(3775.59,4182.48) U4.12 ; v1(4356.3,3984.25) 4391.73,3948.82 4962.73,3948.82 5007.77,3993.86 5084.75,3993.86 5099.86,3978.74 5377.4,3978.74 5404.88,4006.22 5404.88,4007.24 v1(5413.39,4015.75) ; ESP32-S3.9 5344.66,4765.36 v1(5344.66,4718.66) ; v1(5358.27,4220.47) 5358.27,4213.62 5300.4,4155.75 5257.28,4155.75 5219.2,4193.83 5219.2,4526.15 5404.12,4711.07 v1(5415.8,4711.07)
  Bottom Layer w10: v1(3775.59,4182.48) 3775.59,4095.51 4065.74,3805.35 4189.08,3805.35 4356.3,3972.58 v1(4356.3,3984.25) ; v1(5344.66,4718.66) 5339.59,4713.59 5339.59,4711.59 5342.52,4708.66 5413.39,4708.66 v1(5415.8,4711.07) ; v1(5358.27,4220.47) 5404.88,4173.86 5404.88,4024.25 v1(5413.39,4015.75)
UART2_TX: ESP32-S3.8 U4.11 | length 3050.6
  Top Layer w10: U4.11 3862.31,4232.48 3984.85,4109.94 3984.85,3853.74 v1(4011.81,3826.77) ; v1(4401.57,3982.28) 4421.02,3962.83 4956.93,3962.83 5001.97,4007.87 5090.55,4007.87 5105.67,3992.76 5359.92,3992.76 5373.39,4006.22 5373.39,4007.24 v1(5381.89,4015.75) ; v1(5358.27,4181.1) 5345.57,4181.1 5306.2,4141.73 5251.48,4141.73 5205.18,4188.03 5205.18,4531.95 5384.43,4711.21 ESP32-S3.8
  Bottom Layer w10: v1(4011.81,3826.77) 4047.24,3791.34 4194.88,3791.34 4354.96,3951.42 4375.67,3951.42 4401.57,3977.33 v1(4401.57,3982.28) ; v1(5358.27,4181.1) 5377.82,4181.1 5390.39,4168.53 5390.39,4024.25 v1(5381.89,4015.75)
USB_5V: F1.1 USB.B4 USB.B9 | length 1916.5
  Top Layer w39.37: v1(4204.72,4874.02) v1(4256.12,4874.02) v1(4303.15,4874.02) v1(4352.36,4874.02) 4588.58,4874.02 4647.64,4874.02 F1.1
  Bottom Layer w39.37: v1(3500,5393.7) v1(3500,5299.21) 3500,5283.46 v1(3523.62,5259.84) 3544.29,5239.17 v1(3572.44,5239.17) 3733.07,5239.17 3771.46,5277.56 3771.46,5425.05 3800.96,5454.56 3840.2,5454.56 4011.95,5282.8 4011.95,5118.89 4084.06,5046.79 4084.06,5004.33 cw(c4125.99,4930.71) 4210.71,4930.71 cw(c4125.99,4930.71) 4199.61,4888.78 4204.72,4883.66 v1(4204.72,4874.02)
  other v1: 3476.38,5259.84 3476.38,5346.46 3518.62,5346.46
pads on no net: "18-26V MAX.3" "18-26V MAX.4" "OLED SSD1306.5" BUZZER2.3 BUZZER2.4 ESP32-S3.6 ESP32-S3.7 ESP32-S3.12 ESP32-S3.15 ESP32-S3.17 ESP32-S3.18 ESP32-S3.19 ESP32-S3.20 ESP32-S3.21 ESP32-S3.22 ESP32-S3.23 ESP32-S3.24 ESP32-S3.25 ESP32-S3.26 ESP32-S3.27 ESP32-S3.36 ESP32-S3.37 RN1.4 RN1.5 RS232.1 RS232.4 RS232.6 RS232.7 RS232.8 RS232.9 RS232.10 RS232.11 RST.2 RST.4 SW2.2 SW2.4 SW3.2 SW3.4 SW4.2 SW4.4 U7.5 U7.6 USB.9 USB.10 USB.11 USB.12

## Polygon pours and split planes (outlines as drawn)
5V on Bottom Layer (solid, remove dead copper, pour order 16): 4728.35,4535.43 4807.09,4535.43 4807.09,4456.69 4728.35,4456.69
GND on Bottom Layer (solid, remove dead copper, pour order 24): 3000,6838.58 6141.73,6838.58 6141.73,3090.55 3000,3090.55
GND on Top Layer (solid, remove dead copper, pour order 8): 3045.28,6811.02 5919.29,6811.02 5919.29,3000 3045.28,3000
6S_IN on Top Layer (solid, remove dead copper, pour order 2): 3744.09,5457.3 3940.94,5457.3 3940.94,5181.1 3744.09,5181.1
6S_IN on Bottom Layer (solid, remove dead copper, pour order 12): 3673.23,4921.26 3814.96,4921.26 3814.96,4740.16 3673.23,4740.16
USB_5V on Top Layer (solid, remove dead copper, pour order 4): 3444.88,5428.15 3596.06,5428.15 3596.06,5228.35 3444.88,5228.35
USB_5V on Bottom Layer (solid, remove dead copper, pour order 14): 3450.3,5423.69 3537.78,5423.69 3537.78,5239.17 3450.3,5239.17
GND on Top Layer (solid, remove dead copper, pour order 10): 3533.85,5463.39 3730.89,5463.39 3730.89,5277.41 3533.85,5277.41
USB_5V on Bottom Layer (solid, remove dead copper, pour order 20): 4185.04,4913.39 4376.43,4913.39 4376.43,4824.8 4185.04,4824.8
5V on Bottom Layer (solid, remove dead copper, pour order 22): 4882.36,3760.18 5070.87,3760.18 5070.87,3614.17 4882.36,3614.17

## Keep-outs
Board Outline Layer:
  lines w3.94: 3338.68,3966.62 3338.68,6044.82 cw(c3417.42,6044.82) 3417.42,6123.56 3500.52,6123.56 ccw(c3500.52,6202.3) 3578.64,6192.46 cw(c4125.5,6123.56) 4125.5,6674.74 5713.47,6674.74 cw(c5713.47,6596) 5792.21,6596 5792.21,3415.44 cw(c5713.47,3415.44) 5713.47,3336.7 4125.5,3336.7 cw(c4125.5,3887.88) 3578.64,3818.98 ccw(c3500.52,3809.14) 3500.52,3887.88 3417.42,3887.88 cw(c3417.42,3966.62) 3338.68,3966.62

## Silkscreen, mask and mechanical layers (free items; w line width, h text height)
Top Silkscreen Layer:
  lines w10: 4637.8,5838.58 4805.97,5838.58 ; 4726.38,5758.68 4726.38,5917.32
  text "GND" at 4253.94,5100.39 h51.18
  text "3V3" at 4568.9,5100.39 h51.18
Bottom Silkscreen Layer:
  text "6S Li-Po" at 3683.07,6005.91 h78.74 r90
  text "♪(´▽｀)" at 4913.39,5631.89 h196.85
  text "USB-C / 5V IN" at 3564.96,5435.04 h66.93 r90
  text "RS232" at 3486.22,4608.27 h78.74 r90
  text "COSTUMIZED CTRL 2026_ V2" at 4263.78,3427.17 h118.11 r270
  text "特注制禦器コントローラー / 『試作Δ型-Ⅱ』" at 4450.79,3427.17 h157.48 r270

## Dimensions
5277.17,4930.71 to 5277.17,3907.09 on Document Layer
4125.99,5099.02 to 5031.5,5099.02 on Document Layer
4112.21,3026.94 to 5029.53,3026.94 on Document Layer
6409.45,4844.09 to 6409.45,3907.09 on Document Layer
